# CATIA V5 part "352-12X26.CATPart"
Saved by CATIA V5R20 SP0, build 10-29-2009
Part number: 352-12X26
Definition: NONE
Nomenclature: 352-12X26
Source: Unknown
Description: 352-12X26
Bounding box of the stored display mesh (mm): x 0 to 26, y -9 to 9, z -9 to 9
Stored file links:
  C:\Users\Utente\Desktop\IO LAVORO\3D X SITO CF\X SITO\PLASTICA\352\352-12X26.CATPart
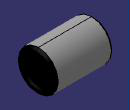
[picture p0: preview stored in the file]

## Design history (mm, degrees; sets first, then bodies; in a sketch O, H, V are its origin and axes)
Body1 "352-12X26" (main body)
  Solid1: solid without history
